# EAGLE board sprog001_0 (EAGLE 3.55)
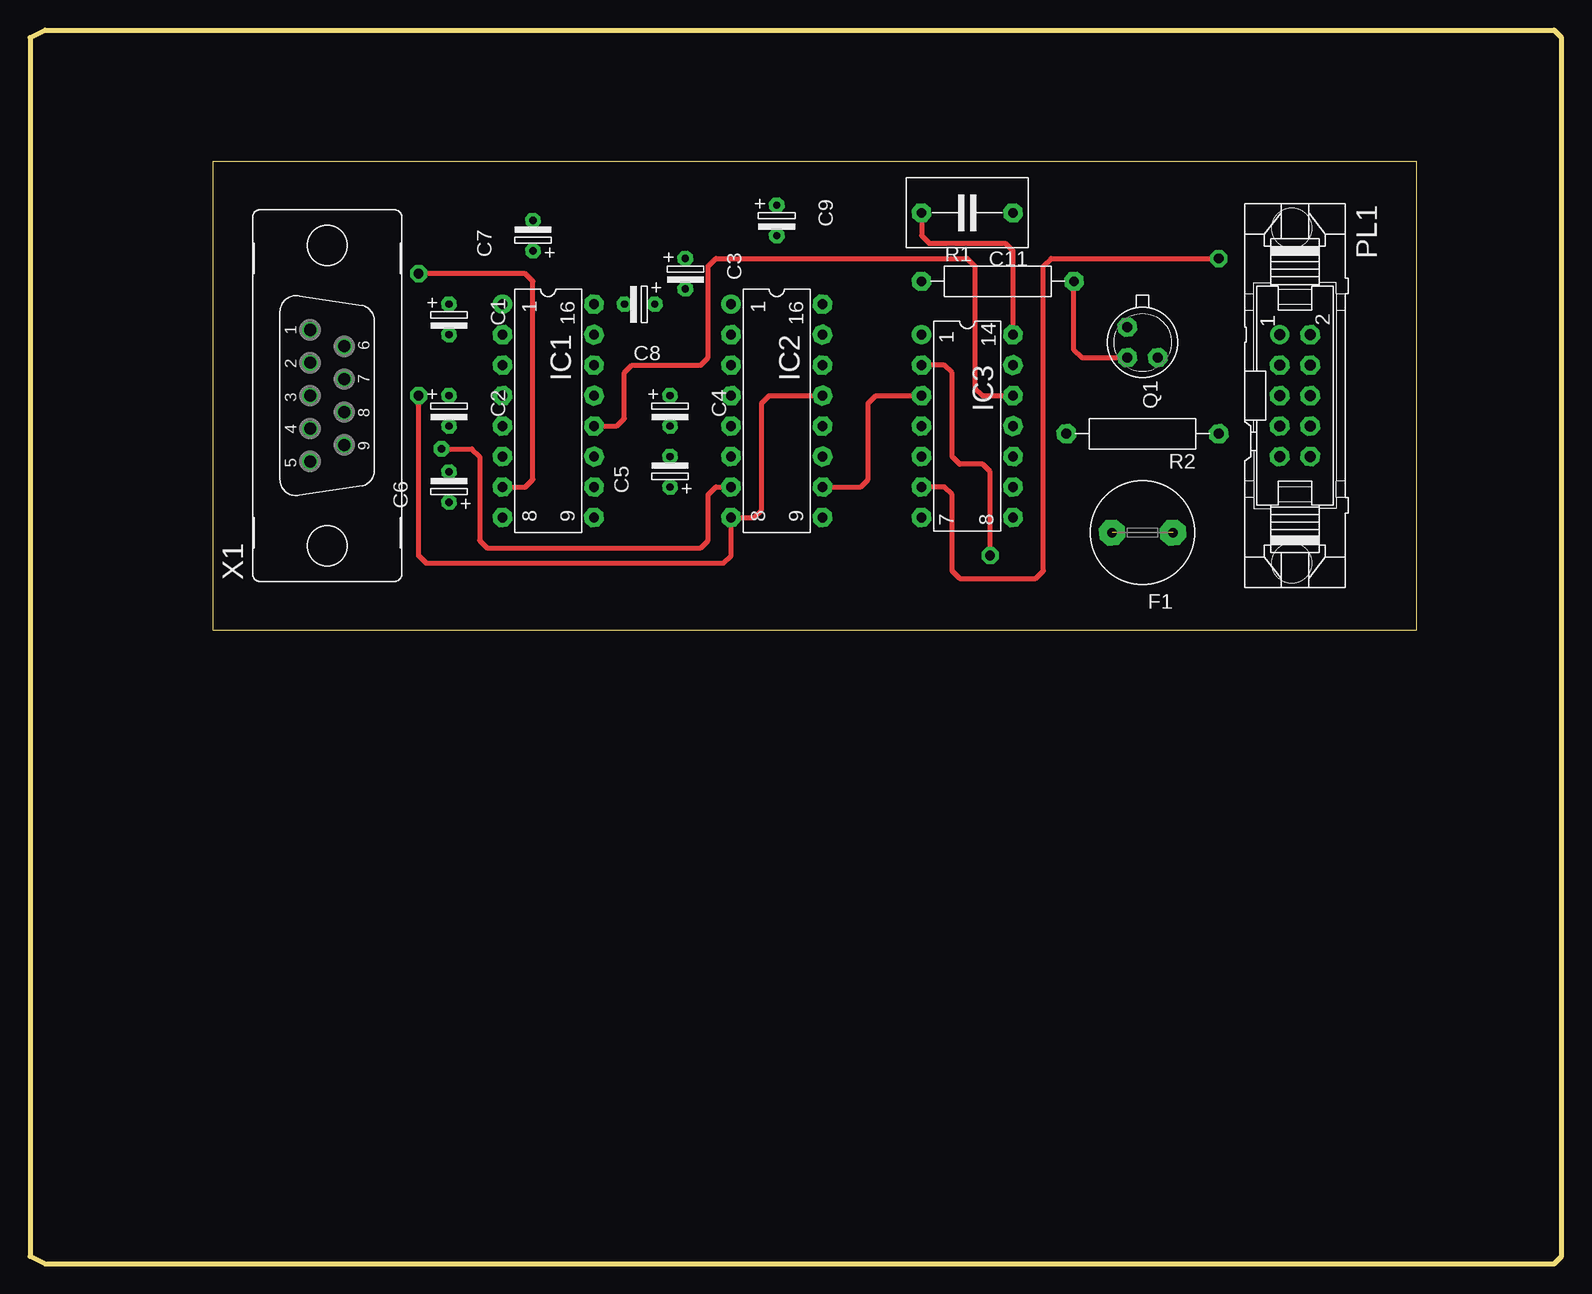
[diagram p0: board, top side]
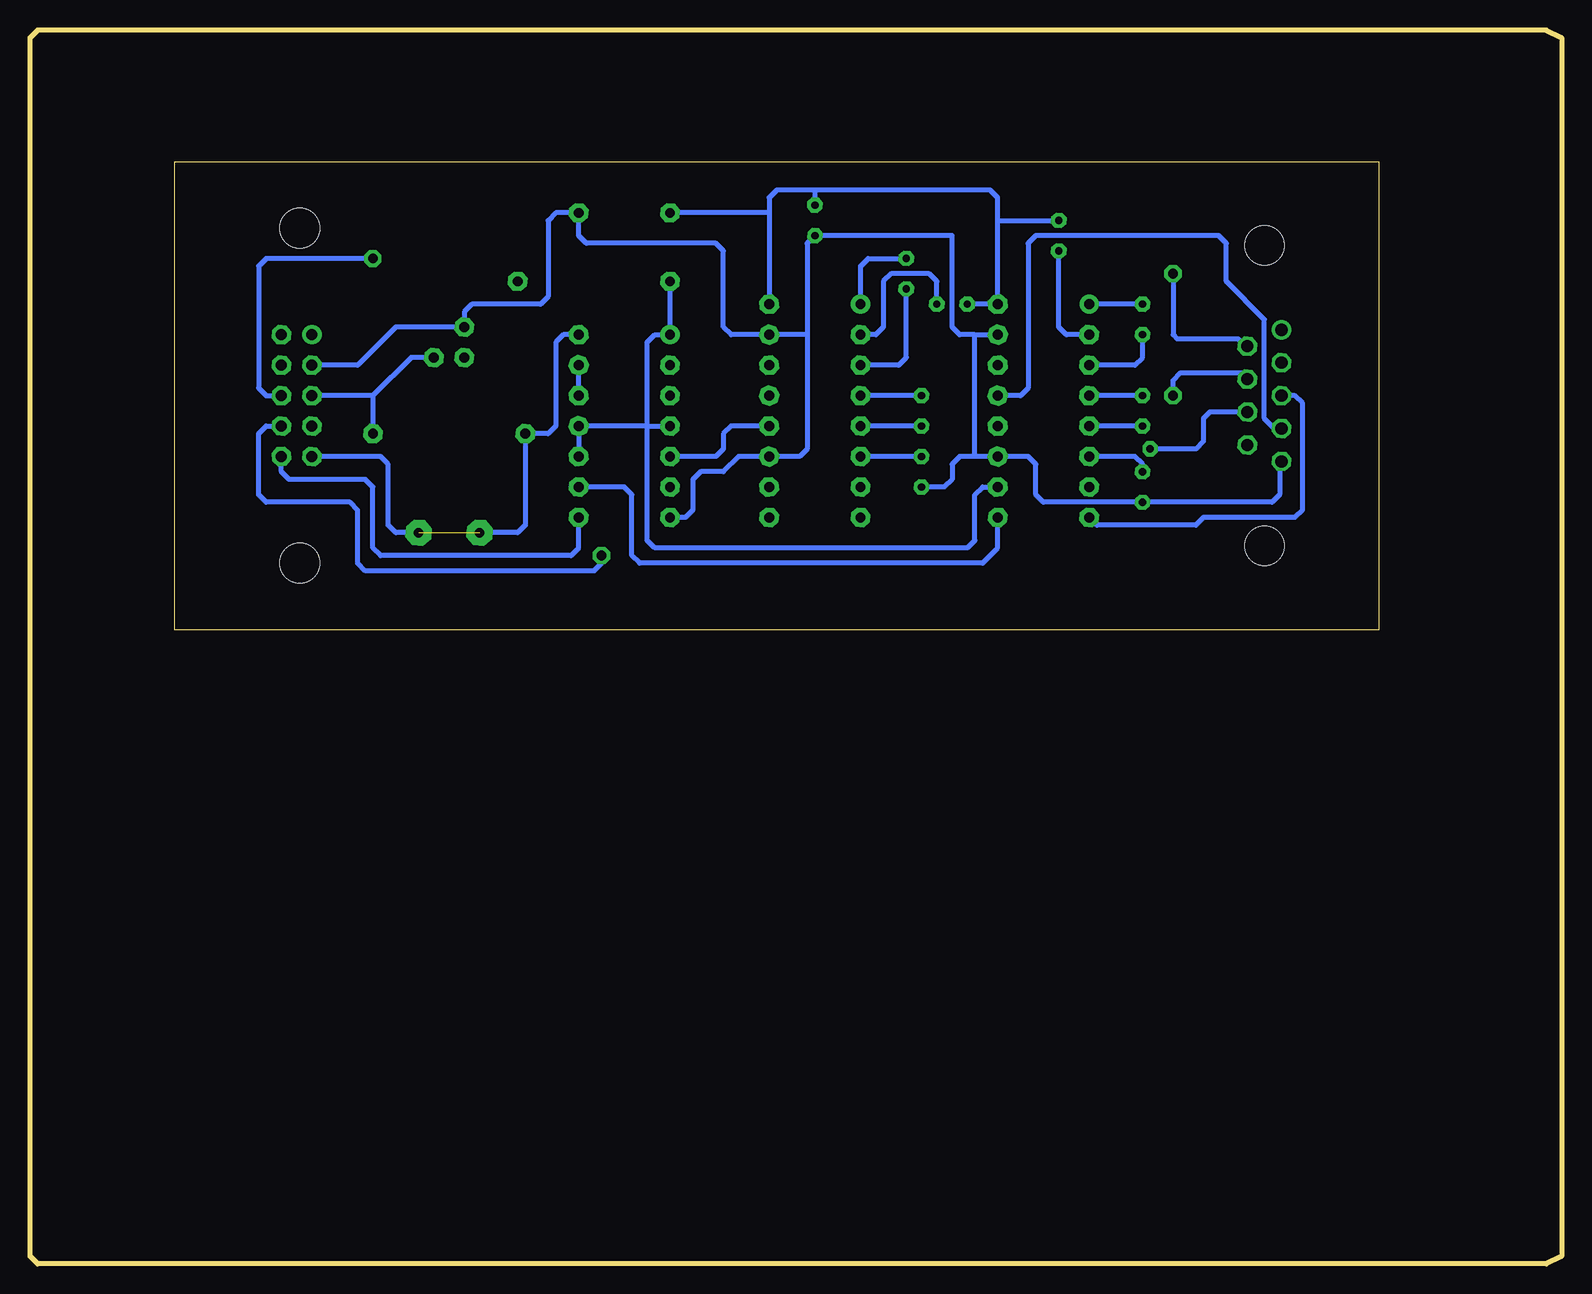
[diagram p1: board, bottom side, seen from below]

Size 127.64 x 102.87 mm. Coordinates in mm from the lower left corner, seen from the top.
Outline: 115.56,52.87 115.56,91.91 15.24,91.91 15.24,52.87 115.56,52.87
Outline: 0,0.63 1.27,0 127,0 127.64,0.63 127.64,102.23 127,102.87 1.27,102.87 0,102.23 0,0.63
Copper layers used: Top, Bottom
vRestrict: area 69.9,50.8 to 94,74.9

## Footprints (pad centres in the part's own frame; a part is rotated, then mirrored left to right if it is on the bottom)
-2,5 = drill 0.61 pad 1.27 octagon:  -1.27,0;  1.27,0
7,5 = drill 0.813 pad 1.6 octagon:  -3.81,0;  3.81,0
5 = drill 0.813 pad 2.159 octagon:  -2.54,0;  2.54,0
L16 = drill 0.813 pad 1.6 round:  -8.89,-3.81 | drill 0.813 pad 1.6 octagon:  -6.35,-3.81;  -3.81,-3.81;  -1.27,-3.81;  1.27,-3.81;  3.81,-3.81;  6.35,-3.81;  8.89,-3.81;  8.89,3.81;  6.35,3.81;  3.81,3.81;  1.27,3.81;  -1.27,3.81;  -3.81,3.81;  -6.35,3.81;  -8.89,3.81
L14 = drill 0.813 pad 1.6 round:  -7.62,-3.81 | drill 0.813 pad 1.6 octagon:  -5.08,-3.81;  -2.54,-3.81;  0,-3.81;  2.54,-3.81;  5.08,-3.81;  7.62,-3.81;  7.62,3.81;  5.08,3.81;  2.54,3.81;  0,3.81;  -2.54,3.81;  -5.08,3.81;  -7.62,3.81
V = drill 0.914 pad 1.6 round:  -5.08,-1.27 | drill 0.914 pad 1.6 octagon:  -5.08,1.27;  -2.54,-1.27;  -2.54,1.27;  0,-1.27;  0,1.27;  2.54,-1.27;  2.54,1.27;  5.08,-1.27;  5.08,1.27 | hole 3.302: 13.97,-0.254; -13.97,-0.254
18A = drill 0.813 pad 1.6 octagon:  -1.27,-1.27;  1.27,-1.27;  1.27,1.27
12,5 = drill 0.813 pad 1.6 octagon:  -6.35,0;  6.35,0
9V = drill 1.016 pad 1.6 round:  5.486,1.422 | drill 1.016 pad 1.6 octagon:  2.743,1.422;  0,1.422;  -2.743,1.422;  -5.486,1.422;  4.115,-1.422;  1.372,-1.422;  -1.372,-1.422;  -4.115,-1.422 | hole 3.302: -12.522,0; 12.522,0

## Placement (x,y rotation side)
C1  10uF  [-2,5]  34.92,78.74 270 top
C2  10uF  [-2,5]  34.92,71.12 270 top
C3  10uF  [-2,5]  54.61,82.55 270 top
C4  10uF  [-2,5]  53.34,71.12 270 top
C5  10uF  [-2,5]  53.34,66.04 90 top
C6  10uF  [-2,5]  34.92,64.77 90 top
C7  10uF  [-2,5]  41.91,85.73 90 top
C8  10uF  [-2,5]  50.8,80.01 180 top
C9  10uF  [-2,5]  62.23,87 270 top
C11  100nF  [7,5]  78.1,87.63 180 top
F1  100mA  [5]  92.71,60.96 180 top
IC1  MAX232  [L16]  43.18,71.12 270 top
IC2  MAX232  [L16]  62.23,71.12 270 top
IC3  74126  [L14]  78.1,69.85 270 top
PL1  10V  [V]  105.41,72.39 270 top
Q1  BC107  [18A]  92.71,76.84 270 top
R1  47k  [12,5]  80.64,81.92 0 top
R2  4k7  [12,5]  92.71,69.22 180 top
X1  F09V  [9V]  24.77,72.39 90 top

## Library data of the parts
C1-C9 C11 R1 R2 = discrete
F1 = fuse
IC1 IC2 = maxim
IC3 = 74xx
PL1 = pinh-v
Q1 = trans-sm
X1 = subd

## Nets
GND: C5. C6. C9. C11. IC1. IC2. IC3. PL1. Q1. X1.
N$1: IC1. X1.
N$2: IC1. X1.
N$3: IC1. X1.
N$4: IC2. X1.
N$5: IC2. X1.
N$6: IC1. IC3.
N$7: IC3. PL1.
N$9: IC1. IC3.
N$10: IC1. IC3. R1.
N$11: Q1. R1.
N$12: IC2. IC3.
N$13: IC3. PL1.
N$15: PL1. Q1. R2.
N$16: IC2. IC3.
N$17: IC3. PL1.
N$18: C4. IC2.
N$19: C4. IC2.
N$20: C3. IC2.
N$21: C3. IC2.
N$22: C2. IC1.
N$23: C2. IC1.
N$24: C1. IC1.
N$25: C1. IC1.
N$26: C5. IC2.
N$27: C7. IC1.
N$28: C8. IC2.
N$29: C6. IC1.
VCC: C7. C8. C9. C11. F1. IC1. IC2. IC3. PL1. R2.

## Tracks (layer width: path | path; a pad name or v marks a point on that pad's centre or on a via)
GND
  Bottom 0.406: 74.3,62.23 73.03,62.23 72.39,62.86 72.39,65.41 71.75,66.04 69.85,66.04 68.58,67.31 66.04,67.31 63.5,67.31 62.87,67.94 62.87,77.47 | 53.34,64.77 51.44,64.77 50.8,65.41 50.8,66.67 50.16,67.31 48.9,67.31 | 48.9,77.47 46.99,77.47 | 48.9,67.31 48.9,77.47 | 48.9,67.31 46.99,67.31 44.45,67.31 43.81,66.67 43.81,64.14 43.18,63.5 34.92,63.5 24.13,63.5 23.5,64.14 23.5,66.67 23.34,66.83 23.34,66.9 | 62.87,77.47 66.04,77.47 69.22,77.47 69.85,78.11 69.85,84.45 70.48,85.09 81.28,85.09 81.92,85.73 81.92,87.63 83.82,87.63 84.45,87 84.45,80.64 85.09,80.01 90.81,80.01 91.44,79.38 91.44,78.11 97.16,78.11 100.33,74.93 104.14,74.93 | 62.87,77.47 62.87,85.09 C9. 50.8,85.73 50.8,78.11 50.16,77.47 48.9,77.47
N$1  (via drill 0.81 pad 1.42)
  Top 0.406: 39.37,64.77 41.27,64.77 41.91,65.41 41.91,81.92 41.27,82.55 v32.39,82.55
  Bottom 0.406: v32.39,82.55 32.39,77.47 32.05,77.14 26.98,77.14 26.19,76.35 | 26.19,76.35 26.04,76.2 | 26.19,76.35 26.19,76.5
N$2
  Bottom 0.406: 46.99,72.39 45.09,72.39 44.45,73.03 44.45,85.09 43.81,85.73 28.57,85.73 27.94,85.09 27.94,81.92 24.77,78.74 24.77,70.48 23.93,69.65 23.34,69.65
N$3
  Bottom 0.406: 39.37,62.23 38.73,61.59 30.48,61.59 29.84,62.23 22.23,62.23 21.59,62.86 21.59,71.75 22.23,72.39 23.34,72.39 23.5,72.39
N$4  (via drill 0.61 pad 1.27)
  Top 0.406: 58.42,64.77 57.15,64.77 56.52,64.14 56.52,60.33 55.88,59.69 38.1,59.69 37.47,60.33 37.47,67.31 36.83,67.94 v34.29,67.94
  Bottom 0.406: 26.19,71.02 29.31,71.02 29.84,70.48 29.84,68.58 30.48,67.94 v34.29,67.94
N$5  (via drill 0.81 pad 1.42)
  Top 0.406: v32.39,72.39 32.39,59.05 33.02,58.42 57.78,58.42 58.42,59.05 58.42,62.23 60.33,62.23 60.96,62.86 60.96,71.75 61.59,72.39 66.04,72.39
  Bottom 0.406: v32.39,72.39 32.39,73.66 31.75,74.3 26.67,74.3 26.14,73.76 | 26.14,73.76 26.04,73.66 | 26.14,73.76 26.19,73.76
N$6
  Bottom 0.406: 46.99,62.23 46.99,59.69 48.26,58.42 76.84,58.42 77.47,59.05 77.47,64.14 78.1,64.77 81.92,64.77 82.55,64.77
N$7
  Bottom 0.406: 81.92,62.23 81.92,59.69 82.55,59.05 98.42,59.05 99.06,59.69 99.06,64.77 99.69,65.41 106.05,65.41 106.68,66.04 PL1.
N$9
  Top 0.406: 46.99,69.85 48.9,69.85 49.53,70.48 49.53,74.3 50.16,74.93 55.88,74.93 56.52,75.56 56.52,83.19 57.15,83.82 78.1,83.82 78.74,83.19 78.74,73.03 79.38,72.39 81.92,72.39
  Bottom 0.406: 81.92,72.39 81.92,74.93
N$10
  Bottom 0.406: 81.92,67.31 81.92,69.85 76.2,69.85 | 76.2,69.85 76.2,60.33 75.56,59.69 49.53,59.69 48.9,60.33 48.9,64.14 48.26,64.77 46.99,64.77 | 76.2,69.85 76.2,76.84 75.56,77.47 74.3,77.47 74.3,81.92 | 76.2,69.85 74.3,69.85
N$11
  Top 0.406: R1. 87,76.2 87.63,75.56 91.44,75.56
N$12
  Bottom 0.406: 74.3,67.31 70.48,67.31 69.85,67.94 69.85,69.22 69.22,69.85 66.04,69.85
N$13  (via drill 0.81 pad 1.42)
  Top 0.406: 74.3,64.77 76.2,64.77 76.84,64.14 76.84,57.78 77.47,57.15 83.82,57.15 84.45,57.78 84.45,83.19 85.09,83.82 v99.06,83.82
  Bottom 0.406: 106.68,72.39 107.95,72.39 108.58,73.03 108.58,83.19 107.95,83.82 v99.06,83.82
N$15
  Bottom 0.406: 99.06,72.39 99.06,69.22 | Q1. 95.89,75.56 99.06,72.39 | 99.06,72.39 104.14,72.39
N$16
  Top 0.406: 66.04,64.77 69.22,64.77 69.85,65.41 69.85,71.75 70.48,72.39 74.3,72.39
N$17  (via drill 0.81 pad 1.42)
  Top 0.406: 74.3,74.93 76.2,74.93 76.84,74.3 76.84,67.31 77.47,66.67 79.38,66.67 80.01,66.04 v80.01,59.05
  Bottom 0.406: v80.01,59.05 80.01,58.42 80.64,57.78 99.69,57.78 100.33,58.42 100.33,62.86 100.97,63.5 107.95,63.5 108.58,64.14 108.58,69.22 107.95,69.85 106.68,69.85
N$18
  Bottom 0.406: C4. 58.42,69.85
N$19
  Bottom 0.406: 53.34,72.39 58.42,72.39
N$20
  Bottom 0.406: C3. 54.61,75.56 55.24,74.93 58.42,74.93
N$21
  Bottom 0.406: 58.42,80.01 58.42,83.19 57.78,83.82 54.61,83.82
N$22
  Bottom 0.406: C2. 39.37,69.85
N$23
  Bottom 0.406: 34.92,72.39 39.37,72.39
N$24
  Bottom 0.406: C1. 34.92,75.56 35.56,74.93 39.37,74.93
N$25
  Bottom 0.406: 34.92,80.01 39.37,80.01
N$26
  Bottom 0.406: C5. 58.42,67.31
N$27
  Bottom 0.406: 39.37,77.47 41.27,77.47 41.91,78.11 41.91,84.45
N$28
  Bottom 0.406: 52.07,80.01 52.07,81.92 52.7,82.55 55.88,82.55 56.52,81.92 56.52,78.11 57.15,77.47 58.42,77.47
N$29
  Bottom 0.406: 39.37,67.31 35.56,67.31 34.92,66.67 C6.
VCC  (1 unrouted)
  Top 0.406: IC3. 81.92,84.45 81.28,85.09 74.93,85.09 74.3,85.73 C11.
  Bottom 0.406: 46.99,87 46.99,88.9 47.62,89.53 62.23,89.53 | 62.23,89.53 62.23,88.27 | 62.23,89.53 65.41,89.53 66.04,88.9 66.04,87.63 | 66.04,87.63 IC2. | IC3. 83.19,77.47 83.82,76.84 83.82,69.85 84.45,69.22 R2. 86.36,61.59 87,60.96 F1. | 95.25,60.96 97.16,60.96 97.79,61.59 97.79,66.67 98.42,67.31 104.14,67.31 | 66.04,87.63 C11. | 46.99,87 C7. | 46.99,87 IC1. C8.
